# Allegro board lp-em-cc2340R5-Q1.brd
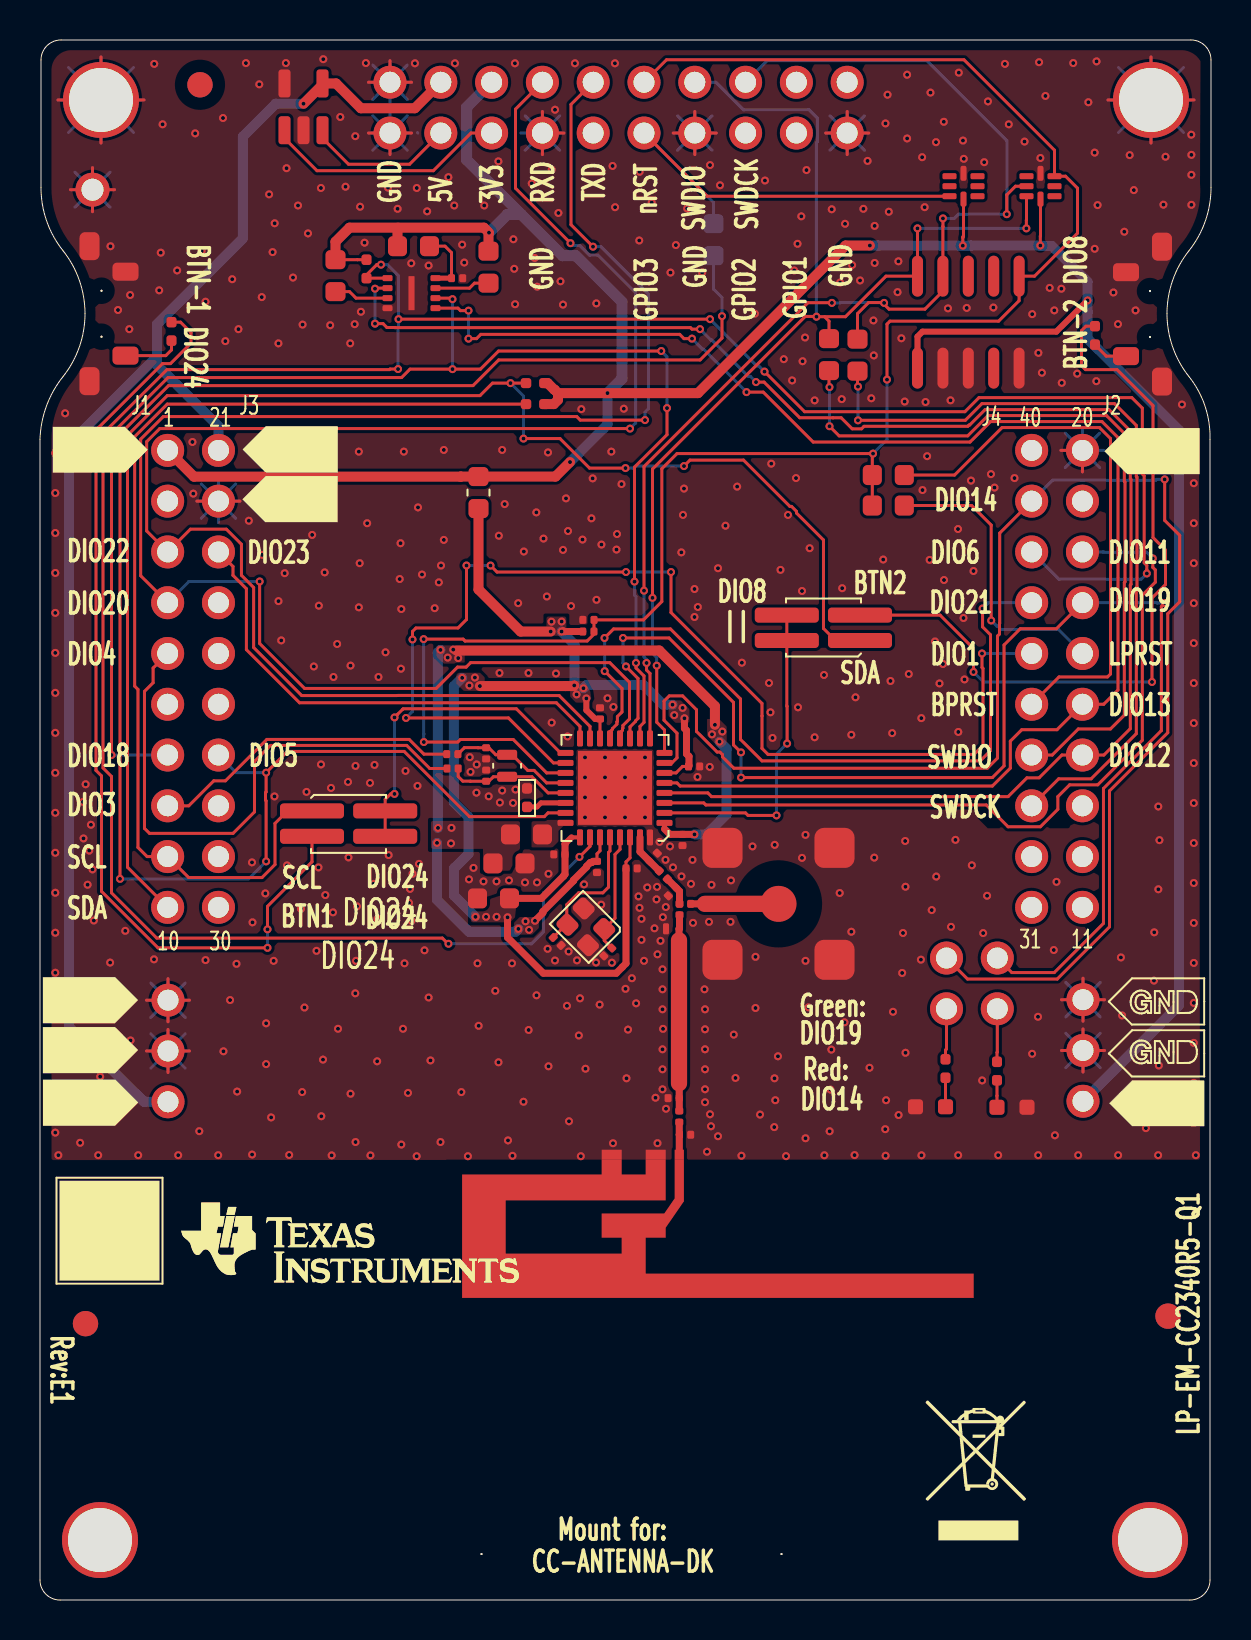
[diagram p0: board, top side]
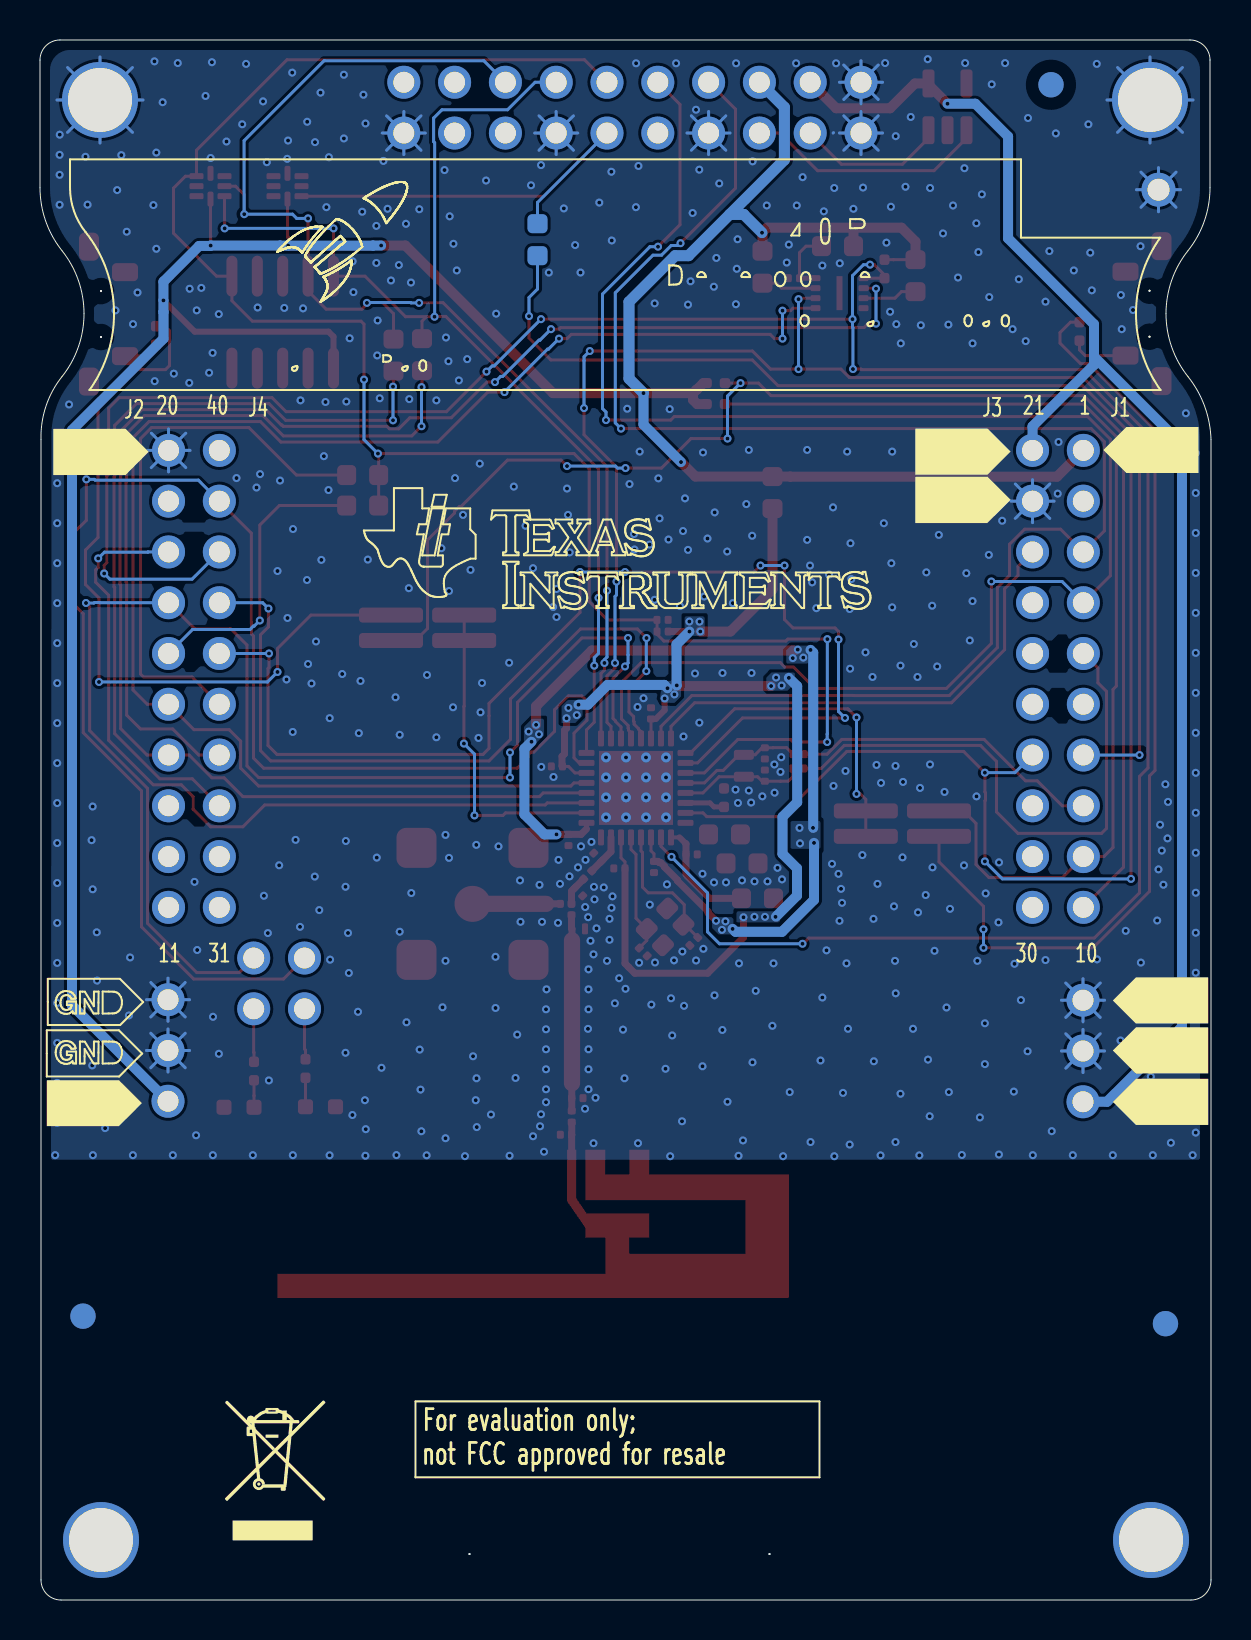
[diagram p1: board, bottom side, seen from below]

Outline 58.55 x 78.04 mm; copper layers: TOP, BOTTOM. Coordinates in mm from the lower left corner of the outline.
Outline path: 0,58.05 0,1 arc(0.29,0.29) 1,0 57.5,0 arc(58.21,0.29) 58.5,1 58.5,58.05 arc(58.25,59.72) 57.45,61.2 arc(56.63,62.68) 56.35,64.35 arc(56.63,66.02) 57.45,67.5 arc(58.27,68.98) 58.55,70.65 58.55,77.04 arc(58.26,77.75) 57.55,78.04 1.05,78.04 arc(0.34,77.75) 0.05,77.04 0.05,70.65 arc(0.33,68.98) 1.15,67.5 arc(1.97,66.02) 2.25,64.35 arc(1.97,62.68) 1.15,61.2 arc(0.32,59.72) 0,58.05

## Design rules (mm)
constraint set DEFAULT: min track width 0.15
nets with their own width: min track width 0.15; nets GND VDDR VDDS WMCU_VDD

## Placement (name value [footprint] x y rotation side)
ANT1  2.4GHz  [ANTENNA_DN007AN]  31.97 22.28 180 top
B1  0  [RESC1608X55A2N]  21.93 54.6 90 top
C9  1uF  [CAPC1005X60B2N]  24.35 39.68 90 top
C33  0.9pF  [CAPC0603X35B2N]  30.86 37.36 225 top
C34  0.9pF  [CAPC0603X35B2N]  31.42 35.23 45 top
C52  7.5pF  [CAPC0603X35B2N]  28.59 32.62 225 top
C53  7.5pF  [CAPC0603X35B2N]  25.66 33.14 315 top
C55  0.1uF  [CAPC0603X35B2N]  20.57 66.12 0 top
C81  12pF  [CAPC0603X35B2N]  22.31 42.63 270 top
C91  15pF  [CAPC0603X35B2N]  22.31 40.96 90 top
C92  0.1uF  [CAPC0603X35B2N]  27.7 49.03 180 top
C99  0.1uF  [CAPC0603X35B2N]  32.43 41.7 0 top
C101  0.1uF  [CAPC0603X35B2N]  28 44.08 90 top
C102  0.1uF  [CAPC0603X35B2N]  29.3 36.6 0 top
C103  0.1uF  [CAPC0603X35B2N]  26.25 37.3 180 top
C104  10uF  [CAPC1608X100A2N]  23.47 35.1 180 top
C105  10uF  [CAPC1608X100A2N]  22.65 36.85 0 top
C106  0.1uF  [CAPC0603X35B2N]  32.12 38.3 270 top
C107  0.1uF  [CAPC0603X35B2N]  27.85 36.95 270 top
CA1  15pF  [CAPC0603X35B2N]  31.97 34.83 0 top
CA2  15pF  [CAPC0603X35B2N]  31.97 34.28 90 top
CR1  LPL296-J2L2-25  [LEDC1707X65N]  49.35 24.65 180 top
CR2  LS L296-P2Q2-1  [LEDC1708X67N]  43.78 24.68 0 top
CR8  TPD6E004RSE  [QFNFC50P150X150X60-8A2N]  50.72 70.23 90 top
CR9  TPD6E004RSE  [QFNFC50P150X150X60-8A2N]  46.88 70.23 90 top
CR10  TPD1E0B04DPY  [SON65P100X60X45-2A2N]  31.3 33.58 0 top
FIDU1  FIDU_1.27mm  [FID127X142]  8 75.8 0 top
FIDU2  FIDU_1.27mm  [FID127X142]  2.28 13.83 0 top
FIDU3  FIDU_1.27mm  [FID127X142]  56.4 14.2 0 top
FIDU4  FIDU_1.27mm  [FID127X142]  8 75.8 180 bottom
FIDU5  FIDU_1.27mm  [FID127X142]  2.28 13.83 180 bottom
FIDU6  FIDU_1.27mm  [FID127X142]  56.4 14.2 180 bottom
J1  SSQ-110-23-L-D  [SAMTEC_SSQ11023LD_A2B]  6.38 57.51 0 bottom
J2  SSQ-110-23-L-D  [SAMTEC_SSQ11023LD_A2B]  49.58 57.51 0 bottom
J7  SMA-10V21-TGG  [HUSTSAN_SMA10V21TGGAN]  36.93 34.83 0 top
L1  10uH  [INDC1608X100A2N]  23.53 38.3 0 top
L33  2.8nH  [INDC0603X33A2N]  30.97 36.47 315 top
LBL1  TI_LOGO  [TI_LOGO_1]  8.06 19.89 0 top
LBL2  TRASH_7mm  [TRASH_7MM]  44.92 2.98 0 top
LBL3  ESD_LABEL_5x5mm  [ESD_LABEL_5X5]  0.97 15.98 0 top
LBL5  -  [LABEL_FOR_EVALUATION_ONLY]  39.63 6.29 180 bottom
M1  SNT-100-BK-G  [SAMTEC_SNT100BKG]  46.57 28.33 90 top
M2  SNT-100-BK-G  [SAMTEC_SNT100BKG]  49.18 28.33 90 top
M3  DCB-10  [MECH_DCB10_A2B]  3 3 0 top
M4  DCB-10  [MECH_DCB10_A2B]  55.5 3 0 top
M5  DCB-10  [MECH_DCB10_A2B]  3.05 75.04 0 top
M6  DCB-10  [MECH_DCB10_A2B]  55.55 75.04 0 top
MH1  HOLE_3.2mm_PTH  [MTG320_380]  3 3 0 top
MH2  HOLE_3.2mm_PTH  [MTG320_380]  55.5 3 0 top
MH3  HOLE_3.2mm_PTH  [MTG320_380]  3.05 75.04 0 top
MH4  HOLE_3.2mm_PTH  [MTG320_380]  55.55 75.04 0 top
MH5  HOLE_1.1mm_PTH  [MTG110_170]  2.62 70.55 0 top
NOREF  -  []  -2.31 22.34 0 top
NOREF#2  -  []  -2.18 27.62 0 top
NOREF#3  -  []  0.28 64.51 0 top
NOREF#4  -  []  -4.3 56.35 0 top
NOREF#5  -  []  53.24 23.47 0 top
NOREF#6  -  []  0.34 77.74 0 top
NOREF#7  -  []  8.46 55.02 0 top
NOREF#8  -  []  -2.18 25.12 0 top
NOREF#9  -  []  0.9 -39.72 0 top
NOREF#10  -  []  51.5 55.05 0 top
NOREF#11  -  []  0.05 75.03 0 top
NOREF#12  -  []  -2.23 77.42 0 top
NOREF#13  -  []  8.4 52.65 0 top
NOREF#14  #VALUE  [unnamed#2]  22.07 2.3 0 top
NOREF#15  -  []  -45.6 -63.8 0 top
NOREF#16  -  []  53.15 0 90 top
NOREF#17  -  []  116.69 68.47 180 bottom
NOREF#18  -  []  6.62 25.08 180 bottom
NOREF#19  -  []  17.1 52.65 180 bottom
NOREF#20  -  []  6.62 27.58 180 bottom
NOREF#21  -  []  58.27 23.64 180 bottom
NOREF#22  -  []  5.6 56.15 180 bottom
NOREF#23  -  []  6.57 22.38 180 bottom
NOREF#24  -  []  17.24 54.91 180 bottom
NOREF#25  -  []  51.53 78.57 180 bottom
NOREF#26  -  []  60.2 55.05 180 bottom
P1  BB02-HC031-KB1-603000  [GRADCONN_BB02HC031KB1603000_A2B]  52.15 24.95 90 top
P2  BB02-HJ041-KB1-603000  [GRADCONN_BB02HJ041KB1603000_A2B]  45.32 29.58 0 top
P3  CNT-F254-210-GD-850/3.2  [CNT_CNTF254210GD85032_A2B]  17.5 75.93 0 top
P4  FTSH-105-01-F-DV-K  [SAMTEC_FTSH-105-01-F-DV-K-10L]  43.88 61.62 0 top
P5  BB02-HC031-KB1-603000  [GRADCONN_BB02HC031KB1603000_A2B]  6.4 24.93 90 top
P6  FTS-102-01-F-DV  [SAMTEC_FTS10201FDV_A2N]  13.6 39.48 270 top
P7  FTS-102-01-F-DV  [SAMTEC_FTS10201FDV_A2N]  41 48 90 top
R1  100k  [RESC0603X35B2N]  27.7 48.45 180 top
R4  0  [RESC1608X55A2N]  39.45 61.5 90 top
R5  0  [RESC1608X55A2N]  40.88 61.48 90 top
R6  0  [RESC0603X35B2N]  20.9 42.31 180 top
R7  0  [RESC0603X35B2N]  20.35 41.6 0 top
R14  180  [RESC1005X40B2N]  45.28 26.12 90 top
R15  220  [RESC1005X40B2N]  47.85 26 90 top
R21  0  [RESC1608X55A2N]  33.68 67.25 90 bottom
R22  0  [RESC1608X55A2N]  22.43 67.48 270 top
R23  0  [RESC1608X55A2N]  14.78 67.05 270 top
R24  2.2k  [RESC1005X40B2N]  16.32 66.12 90 top
R25  0  [RESC1608X55A2N]  19.47 67.73 180 top
R51  0  [RESC1608X55A2N]  43.22 54.75 180 top
R52  0  [RESC1608X55A2N]  43.22 56.28 180 top
R55  100  [RESC1005X40B2N]  52.75 62.8 90 top
R56  100  [RESC1005X40B2N]  6.57 63 90 top
R66  3.3k  [RESC1005X40B2N]  24.3 60.88 0 top
R67  3.3k  [RESC1005X40B2N]  24.3 59.83 0 top
SW1  1188E-1K2  [SW_1188E1K2V_A2N]  2.47 67.73 270 top
SW2  1188E-1K2  [SW_1188E1K2V_A2N]  56.1 60.95 90 top
U1  CC2340R52E0RHB  [QFNFC50P500X500X100-33B2N]  31.22 38.88 90 top
U3  MX25R8035FZUIL0  [SON50P300X200X60-9B2N]  17.38 66.12 270 top
U4  CAT24C08TDI  [SOT95P280X100-5A2N]  12.22 73.53 0 top
UNK#REFDES  #VALUE  []  46.65 66.21 180 bottom
Y1  32.768KHz  [XTAL_TZ3359DAAO73_A2N]  23.36 42.28 270 top
Y2  48MHz  [OSCCC205X165X50-4A2N]  28.21 33.57 135 top
Z60  TBD  [CAPC0603X35B2N]  31.96 25.11 180 top
Z61  0  [RESC0603X35B2N]  31.96 23.91 90 top
Z62  TBD  [CAPC0603X35B2N]  31.97 23.28 0 top

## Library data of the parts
ANT1 = ANTENNA_DN007
B1 R4 R5 R21-R23 R25 R51 R52 = RESISTOR: User Part Number: #PN; alternate symbols: (RESC1608X55A2L,RESC1608X55A2M)
C9 = CAPACITOR: User Part Number: #PN
C33 C34 C52 C53 C55 C81 C91 C92 C99 C101-C103 C106 C107 CA1 CA2 Z60 Z62 = CAPACITOR: User Part Number: #PN; alternate symbols: (CAPC0603X35B2L,CAPC0603X35B2M)
C104 C105 = CAPACITOR: User Part Number: #PN; alternate symbols: (CAPC1608X100A2L,CAPC1608X100A2M)
CR1 = LED: alternate symbols: (LEDC1707X65L,LEDC1707X65M)
CR2 = LED: alternate symbols: (LEDC1708X67L,LEDC1708X67M)
CR8 CR9 = DIODE_TVS_TPD6E004_QFN8_V1: User Part Number: #PN; alternate symbols: (QFNFC50P150X150X60-8A2L,QFNFC50P150X150X60-8A2M)
CR10 = DIODE_TVS_BIDIR_S: User Part Number: #PN
FIDU1-FIDU6 = FIDMARK
J1 J2 = CONN_HEADER_2X10_J_S_V1: User Part Number: #PN; alternate symbols: (SAMTEC_SSQ11023LD_A2C,SAMTEC_SSQ11023LD_A2A)
J7 = CONN_COAX_1_4: alternate symbols: (HUSTSAN_SMA10V21TGGL,HUSTSAN_SMA10V21TGGM)
L1 = IND_CORE: User Part Number: #PN; alternate symbols: (INDC1608X100A2L,INDC1608X100A2M)
L33 = INDUCTOR: User Part Number: #PN; alternate symbols: (INDC0603X33A2L,INDC0603X33A2M)
LBL1 = TI_LOGO_V1
LBL2 = TRASH_V2: User Part Number: #PN
LBL3 = ESD_LABEL: User Part Number: #PN
LBL5 = LABEL_FOR_EVALUATOIN_ONLY: User Part Number: #PN
M1 M2 = MECH_SHUNT_JUMPER_V1: User Part Number: #PN
M3-M6 = MECH_SPACERS_SUPPORT_V1: User Part Number: #PN
MH1-MH5 = HOLE_PTH
NOREF#14 UNK#REFDES = -: User Part Number: #PN
P1 P5 = CONN_HEADER_3_P_S: User Part Number: #PN; alternate symbols: (GRADCONN_BB02HC031KB1603000_A2C,GRADCONN_BB02HC031KB1603000_A2A)
P2 = CONN_HEADER_2X2_P: User Part Number: #PN; alternate symbols: (GRADCONN_BB02HJ041KB1603000_A2C,GRADCONN_BB02HJ041KB1603000_A2A)
P3 = CONN_HEADER_2X10_J_S_V1: User Part Number: #PN; alternate symbols: (CNT_CNTF254210GD85032_A2A,CNT_CNTF254210GD85032_A2C)
P4 = CONN_HEADER_2X5: alternate symbols: (SAMTEC_FTSH10501FDVK_A2L,SAMTEC_FTSH10501FDVK_A2M)
P6 P7 = CONN_HEADER_2X2_P_V2: User Part Number: #PN; alternate symbols: (SAMTEC_FTS10201FDV_A2L,SAMTEC_FTS10201FDV_A2M)
R1 R6 R7 Z61 = RESISTOR: User Part Number: #PN; alternate symbols: (RESC0603X35B2L,RESC0603X35B2M)
R14 R15 R24 R55 R56 R66 R67 = RESISTOR: User Part Number: #PN
SW1 SW2 = SWITCH_TACT_V2: alternate symbols: (SW_1188E1K2V_A2L,SW_1188E1K2V_A2M)
U1 = IC_CC2340R52E0RHB_VQFN32: User Part Number: #PN; alternate symbols: (QFNFC50P500X500X100-33B2L,QFNFC50P500X500X100-33B2M)
U3 = IC_FLASH_MX25R8035F_USON8: User Part Number: #PN; alternate symbols: (SON50P300X200X60-9B2L,SON50P300X200X60-9B2M)
U4 = IC_EEPROM_CAT24C08_TSOT23-5: User Part Number: #PN; alternate symbols: (SOT95P280X100-5A2L,SOT95P280X100-5A2M)
Y1 = XTAL: User Part Number: #PN; alternate symbols: (XTAL_TZ3359DAAO73_A2L,XTAL_TZ3359DAAO73_A2M)
Y2 = XTAL_4PINS_1_3: User Part Number: #PN; alternate symbols: (OSCCC205X165X50-4A2L,OSCCC205X165X50-4A2M)

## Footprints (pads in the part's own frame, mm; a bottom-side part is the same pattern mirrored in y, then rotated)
ANTENNA_DN007AN
  rect 0.46x0.5 smd: 1(0,0)
  rect 1.001x0.5 smd: 2(1.18,0) 3(3.38,0)
CAPC0603X35B2N
  custom 0.087x0.087 smd: 1(0,0) 2(0.56,0)
CAPC1005X60B2N
  custom 0.125x0.125 smd: 1(0,0) 2(0.924,0)
CAPC1608X100A2N
  custom 0.237x0.237 smd: 1(0,0) 2(1.6,0)
CNT_CNTF254210GD85032_A2B
  round 1.65 hole 1.05: 1(0,0) 2(0,-2.54) 3(2.54,0) 4(2.54,-2.54) 5(5.08,0) 6(5.08,-2.54) 7(7.62,0) 8(7.62,-2.54) 9(10.16,0) 10(10.16,-2.54) 11(12.7,0) 12(12.7,-2.54) 13(15.24,0) 14(15.24,-2.54) 15(17.78,0) 16(17.78,-2.54) 17(20.32,0) 18(20.32,-2.54) 19(22.86,0) 20(22.86,-2.54)
FID127X142
  round 1.27 smd: 1(0,0)
GRADCONN_BB02HC031KB1603000_A2B
  round 1.65 hole 1.05: 1(0,0) 2(2.54,0) 3(5.08,0)
GRADCONN_BB02HJ041KB1603000_A2B
  round 1.65 hole 1.05: 1(0,0) 2(0,2.54) 3(2.54,0) 4(2.54,2.54)
HUSTSAN_SMA10V21TGGAN
  round 1.8 smd: 1(0,0)
  custom 0.5x0.5 smd: 2(-2.8,-2.8) 3(2.8,-2.8) 4(2.8,2.8) 5(-2.8,2.8)
INDC0603X33A2N
  custom 0.087x0.087 smd: 1(0,0) 2(0.56,0)
INDC1608X100A2N
  custom 0.237x0.237 smd: 1(0,0) 2(1.6,0)
LEDC1707X65N
  custom 0.188x0.188 smd: 1(0,0) 2(1.501,0)
LEDC1708X67N
  custom 0.188x0.188 smd: 1(0,0) 2(1.501,0)
MTG110_170
  round 1.699 hole 1.1: 1(0,0)
MTG320_380
  round 3.8 hole 3.2: 1(0,0)
OSCCC205X165X50-4A2N
  custom 0.212x0.212 smd: 1(0,0) 2(1.45,0) 3(1.45,1.15) 4(0,1.15)
QFNFC50P150X150X60-8A2N
  custom 0.075x0.075 smd: 1(0,0) 2(0.5,0) 3(1,0) 4(1.145,0.7) 5(1,1.4) 6(0.5,1.4) 7(0,1.4) 8(-0.145,0.7)
QFNFC50P500X500X100-33B2N
  custom 0.075x0.075 smd: 1(0,0) 2(0.5,0) 3(1,0) 4(1.5,0) 5(2,0) 6(2.5,0) 7(3,0) 8(3.5,0) 9(4.225,0.725) 10(4.225,1.225) 11(4.225,1.725) 12(4.225,2.225) 13(4.225,2.725) 14(4.225,3.225) 15(4.225,3.725) 16(4.225,4.225) 17(3.5,4.95) 18(3,4.95) 19(2.5,4.95) 20(2,4.95) 21(1.5,4.95) 22(1,4.95) 23(0.5,4.95) 24(0,4.95) 25(-0.725,4.225) 26(-0.725,3.725) 27(-0.725,3.225) 28(-0.725,2.725) 29(-0.725,2.225) 30(-0.725,1.725) 31(-0.725,1.225) 32(-0.725,0.725)
  rect 3.7x3.7 smd: 33(1.75,2.475)
RESC0603X35B2N
  custom 0.087x0.087 smd: 1(0,0) 2(0.56,0)
RESC1005X40B2N
  custom 0.125x0.125 smd: 1(0,0) 2(0.924,0)
RESC1608X55A2N
  custom 0.237x0.237 smd: 1(0,0) 2(1.6,0)
SAMTEC_FTS10201FDV_A2N
  custom 0.188x0.188 smd: 1(0,0) 2(0,3.66) 3(1.27,0) 4(1.27,3.66)
SAMTEC_FTSH-105-01-F-DV-K-10L
  oval 0.551x2.05 smd: 1(0,0) 2(0,4.6) 3(1.27,0) 4(1.27,4.6) 5(2.54,0) 6(2.54,4.6) 7(3.81,0) 8(3.81,4.6) 9(5.08,0) 10(5.08,4.6)
SAMTEC_SSQ11023LD_A2B
  round 1.65 hole 1.05: 1(0,0) 2(2.54,0) 3(0,2.54) 4(2.54,2.54) 5(0,5.08) 6(2.54,5.08) 7(0,7.62) 8(2.54,7.62) 9(0,10.16) 10(2.54,10.16) 11(0,12.7) 12(2.54,12.7) 13(0,15.24) 14(2.54,15.24) 15(0,17.78) 16(2.54,17.78) 17(0,20.32) 18(2.54,20.32) 19(0,22.86) 20(2.54,22.86)
SON50P300X200X60-9B2N
  custom 0.075x0.075 smd: 1(0,0) 2(0.5,0) 3(1,0) 4(1.5,0) 5(1.5,2.4) 6(1,2.4) 7(0.5,2.4) 8(0,2.4)
  rect 1.7x0.3 smd: 9(0.75,1.2)
SON65P100X60X45-2A2N
  custom 0.075x0.075 smd: 1(0,0) 2(0.65,0)
SOT95P280X100-5A2N
  custom 0.15x0.15 smd: 1(0,0) 2(0.95,0) 3(1.9,0) 4(1.9,2.34) 5(0,2.34)
SW_1188E1K2V_A2N
  round 0.099 hole 0.899 unplated: (2.229,0.6) (4.529,0.6)
  custom 0.25x0.25 smd: 1(0,0) 2(6.75,0)
  custom 0.225x0.225 smd: 3(1.275,1.8) 4(5.475,1.8)
unnamed#2
  round 0.099 hole 3.2 unplated: (0,0) (15,0)
XTAL_TZ3359DAAO73_A2N
  custom 0.125x0.125 smd: 1(0,0) 2(1.1,0)

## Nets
5V0_BP: J1.2 P3.3 P5.1 U4.4
GND: ANT1.2 ANT1.3(GND_3) C9.2 C33.1 C34.1 C52.2 C53.2 C55.2 C81.2 C91.2 C92.2 C99.2 C101.2 C102.2 C103.2 C104.2 C105.2 C106.2 C107.2 CR1.1(C) CR2.1(C) CR8.4 CR9.4 CR10.1 J1.4 J2.2 J7.2 J7.3 J7.4 J7.5 MH3.1 MH4.1 MH5.1 P1.2 P1.3 P3.1 P3.2 P3.8 P3.14 P3.20 P4.3 P4.5 P4.9 P5.2 P5.3 SW1.1 SW1.2 SW1.3 SW2.1 SW2.2 SW2.4 U1.32 U1.33 U3.4 U3.9 U4.2 U4.5(WP) Y2.2 Y2.4(GND#4) Z60.2 Z62.2
VDDR: C105.1 C106.1 C107.1 L1.1 U1.1 U1.27
VDDS: B1.1 C99.1 C101.1 C102.1 C103.1 C104.1 R1.2 U1.6 U1.14 U1.25 U1.30
BP_RESET: J2.11 R52.1
BTN1: P6.3 R56.2
BTN2: P7.3 R55.2
DCDC: L1.2 U1.24
DIO1_RTS: J2.9 U1.18
DIO3: J1.15 R6.2
DIO4: J1.9 R7.1
DIO5_A2: J1.14 R21.1 U1.23
DIO6_FLASH_CS: J2.5 R24.1 U1.26 U3.1
DIO8_SDA: P7.2 P7.4 U1.2(DIO8)
DIO11_CS: J2.6 U1.3
DIO12_MISO: J2.14 U1.4 U3.2
DIO13_MOSI: J2.12 U1.5 U3.5
DIO14_RLED: J2.3 P2.2 U1.7
DIO18_SCLK: J1.13 U1.10 U3.6
DIO19_GLED: J2.8 P2.4 U1.11
DIO21_CTS: J2.7 U1.13
DIO23_A8: J1.6 U1.16
DIO24_SCL: P6.2 P6.4 U1.17
LP_RESET: J2.10 R51.1
SCL: J1.17 P6.1 R67.1
SDA: J1.19 P7.1 R66.1
WMCU_RESET: C92.1 CR8.3 P3.11 P4.10 R1.1 R51.2 R52.2 U1.19
WMCU_RXD: J1.5 P3.7 U1.15
WMCU_SWDCK: CR8.6 P3.15 P4.4 R5.2 U1.9
WMCU_SWDIO: CR8.7 P3.13 P4.2 R4.2 U1.8
WMCU_TXD: J1.7 P3.9 U1.12
WMCU_VDD: B1.2 CR8.8(VCC) CR9.8(VCC) J1.1 P1.1 P3.5 P4.1 R22.1 R23.1 R24.2 R25.2 R66.2 R67.2
XDS_BOARDID_SCL: P3.6 U4.1
XDS_BOARDID_SDA: P3.4 U4.3
XDS_GPIO3: CR9.7 P3.12 R21.2
N3101199: C81.1 R6.1 U1.20 Y1.1
N3101441: C52.1 U1.29 Y2.1
N3101453: C53.1 U1.28 Y2.3
N3109894: J2.13 R4.1
N3109960: J2.15 R5.1
N3110356: P2.1 R14.2
N3110380: P2.3 R15.2
N3110768: R56.1 SW1.4
N3110772: R55.1 SW2.3
N3110876: CR1.2 R15.1
N3110880: CR2.2 R14.1
N3111246: C55.1 R25.1 U3.8(VCC)
N3111262: R22.2 U3.7
N3111266: R23.2 U3.3
N3241033: C91.1 R7.2 U1.21 Y1.2
N3275984: CA1.2 J7.1
N3375988: C34.2 CA1.1 CA2.2 L33.2
N3377063: CA2.1 CR10.2 Z60.1 Z61.2
N3377070: ANT1.1 Z61.1 Z62.1
N3512302: C33.2 L33.1 U1.31
N3566095: C9.1 U1.22

Pads without a net: CR8 1 2 5; CR9 1 2 3 5 6; FIDU1 1; FIDU2 1; FIDU3 1; FIDU4 1; FIDU5 1; FIDU6 1; J1 3 8 10 11 12 16 18 20; J2 1 4 16 17 18 19 20; MH1 1; MH2 1; P3 10 16 17 18 19; P4 6 7 8

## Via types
v1: diameter 0.4, hole 0.2, TOP to BOTTOM, 691 vias
v2: diameter 0.5, hole 0.201, TOP to BOTTOM, 16 vias

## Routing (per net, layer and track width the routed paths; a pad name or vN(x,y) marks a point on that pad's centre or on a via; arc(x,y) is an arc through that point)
5V0_BP: length 72.7
  TOP w0.5: v1(13.18,74.85) 14.12,75.8 U4.4 14.8,75.87 16.04,74.62 18.74,74.62 P3.3
  BOTTOM w0.5: 5.85,62.2 1.7,58.05 1.7,57.98 1.45,57.73 1.45,28.67 5.2,24.93 P5.1 ; 5.85,62.2 5.85,63.82 10.15,68.12 10.15,73.21 11.78,74.85 v1(13.18,74.85) ; 5.85,62.2 5.85,61.79 8.92,58.71 J1.2
GND: length 207.5
  TOP w0.15: P1.2 53.23,27.49 ; P1.2 51.07,27.49 ; P1.2 52.15,28.57 ; P1.2 52.15,26.41 ; MH3.1 5.2,75.04 ; MH3.1 3.05,72.89 ; MH3.1 0.9,75.04 ; MH3.1 3.05,77.19 ; P3.20 40.36,74.46 ; P3.20 40.36,72.31 ; P3.20 41.44,73.38 ; P3.20 39.28,73.38 ; MH5.1 2.62,71.65 ; MH5.1 2.62,69.45 ; MH5.1 1.52,70.55 ; MH5.1 3.73,70.55 ; P3.8 25.12,74.46 ; P3.8 25.12,72.31 ; P3.8 26.2,73.38 ; 32.74,72.31 P3.14 ; P3.14 33.82,73.38 ; P3.14 31.66,73.38 ; P3.14 32.74,74.46 ; MH4.1 57.7,75.04 ; MH4.1 55.55,77.19 ; MH4.1 53.4,75.04 ; MH4.1 55.55,72.89 ; P1.3 53.23,30.03 ; P1.3 52.15,28.95 ; P1.3 51.07,30.03 ; P1.3 52.15,31.11 ; P3.1 18.58,75.93 ; P3.1 16.42,75.93 ; P3.1 17.5,77 ; 6.4,26.39 P5.2 ; P5.2 6.4,28.54 ; P5.2 5.32,27.47 ; P5.2 7.48,27.47 ; 17.5,72.31 P3.2 ; P3.2 18.58,73.38 ; P3.2 16.42,73.38 ; 6.4,28.93 P5.3 ; P5.3 5.32,30.01 ; P5.3 7.48,30.01 ; P5.3 6.4,31.08 ; 10,54.97 J1.4 7.85,54.97 ; 51.05,57.51 J2.2 52.12,56.43
  BOTTOM w0.15: 3.05,72.89 MH3.1 ; MH3.1 1.43,76.66 ; MH3.1 3.05,77.19 ; MH3.1 4.67,73.42 ; MH3.1 1.43,73.42 ; MH3.1 0.9,75.04 ; MH3.1 5.2,75.04 ; MH3.1 4.67,76.66 ; P1.2 53.23,27.49 ; P1.2 51.29,28.35 ; P1.2 51.29,26.63 ; P1.2 53.01,28.35 ; P1.2 51.07,27.49 ; P1.2 53.01,26.63 ; P1.2 52.15,28.57 ; P1.2 52.15,26.41 ; P3.1 18.58,75.93 ; P3.1 16.42,75.93 ; P3.1 16.64,75.06 ; P3.1 18.36,76.79 ; P3.1 17.5,74.85 ; P3.1 16.64,76.79 ; P3.1 18.36,75.06 ; P3.1 17.5,77 ; 5.32,30.01 P5.3 ; P5.3 5.54,29.14 ; P5.3 6.4,31.08 ; P5.3 5.54,30.87 ; P5.3 7.26,30.87 ; P5.3 6.4,28.93 ; P5.3 7.26,29.14 ; P5.3 7.48,30.01 ; 24.04,73.38 P3.8 ; P3.8 25.98,74.25 ; P3.8 25.98,72.52 ; P3.8 25.12,72.31 ; P3.8 24.26,72.52 ; P3.8 26.2,73.38 ; P3.8 24.26,74.25 ; P3.8 25.12,74.46 ; 40.36,72.31 P3.20 ; P3.20 39.5,72.52 ; P3.20 39.5,74.25 ; P3.20 39.28,73.38 ; P3.20 41.22,74.25 ; P3.20 41.44,73.38 ; P3.20 41.22,72.52 ; P3.20 40.36,74.46 ; 55.55,72.89 MH4.1 ; MH4.1 57.17,73.42 ; MH4.1 57.17,76.66 ; MH4.1 55.55,77.19 ; MH4.1 53.93,73.42 ; MH4.1 53.93,76.66 ; MH4.1 57.7,75.04 ; MH4.1 53.4,75.04 ; 32.74,72.31 P3.14 ; P3.14 32.74,74.46 ; P3.14 33.82,73.38 ; P3.14 31.88,74.25 ; P3.14 33.6,74.25 ; P3.14 31.66,73.38 ; P3.14 33.6,72.52 ; P3.14 31.88,72.52 ; P3.2 17.5,74.46 ; P3.2 18.36,72.52 ; P3.2 16.42,73.38 ; P3.2 16.64,74.25 ; P3.2 18.58,73.38 ; P3.2 17.5,72.31 ; P3.2 16.64,72.52 ; P3.2 18.36,74.25 ; P1.3 53.01,29.17 ; P1.3 51.29,29.17 ; P1.3 51.29,30.89 ; P1.3 51.07,30.03 ; P1.3 52.15,31.11 ; P1.3 52.15,28.95 ; P1.3 53.01,30.89 ; P1.3 53.23,30.03 ; 51.26,56.65 J2.2 ; J2.2 53.2,57.51 ; J2.2 52.99,56.65 ; J2.2 52.12,56.43 ; J2.2 51.05,57.51 ; J2.2 52.12,58.59 ; J2.2 51.26,58.37 ; J2.2 52.99,58.37 ; 1.75,71.43 MH5.1 ; MH5.1 3.5,69.67 ; MH5.1 1.52,70.55 ; MH5.1 2.62,71.65 ; MH5.1 1.75,69.67 ; MH5.1 3.5,71.43 ; MH5.1 2.62,69.45 ; MH5.1 3.73,70.55 ; J1.4 10,54.97 ; J1.4 8.92,53.89 ; J1.4 8.06,54.11 ; J1.4 8.92,56.05 ; J1.4 7.85,54.97 ; J1.4 9.78,54.11 ; J1.4 9.78,55.83 ; J1.4 8.06,55.83 ; P5.2 7.48,27.47 ; P5.2 7.26,28.33 ; P5.2 6.4,26.39 ; P5.2 7.26,26.6 ; P5.2 6.4,28.54 ; P5.2 5.54,26.6 ; P5.2 5.32,27.47 ; P5.2 5.54,28.33 ; 18.89,73.38 18.88,73.4
  vias: v1(0.76,57.38) v1(0.76,55.38) v1(0.76,53.38) v1(0.76,51.38) v1(0.76,49.38) v1(0.76,47.38) v1(0.76,45.38) v1(0.76,43.38) v1(0.76,41.38) v1(0.76,39.38) v1(0.76,37.38) v1(0.76,35.38) v1(0.76,33.38) v1(0.76,31.38) v1(0.76,29.38) v1(0.76,27.38) v1(0.76,25.38) v1(0.76,23.38) v1(0.92,22.25) v1(1.26,59.37) v1(2.01,22.87) v1(2.15,39.93) v1(2.18,38.1) v1(2.28,40.81) v1(2.38,35.78) v1(2.55,38.78) v1(2.46,37.49) v1(2.62,36.55) v1(2.69,33.99) v1(2.91,22.25) v1(2.98,30.08) v1(3.01,26.18) v1(3.52,67.72) v1(3.51,31.89) v1(3.55,24.1) v1(3.9,64.53) v1(4.26,33.48) v1(4.51,65.28) v1(4.46,63.57) v1(4.53,27.99) v1(4.91,22.25) v1(5.71,76.84) v1(5.7,32.05) v1(6.04,67.4) v1(5.96,65.52) v1(6.13,73.82) v1(6.86,66.51) v1(6.91,22.25) v1(7.62,57.93) v1(7.66,55.35) v1(7.76,73.37) v1(7.96,23.45) v1(8.08,67.48) v1(8.28,64.95) v1(8.28,32.01) v1(8.91,22.25) v1(9.15,74.14) v1(9.17,27.45) v1(9.27,62.98) v1(9.5,30.01) v1(9.61,66.07) v1(9.82,31.83) v1(9.92,63.57) v1(9.86,25.43) v1(10.3,76.88) v1(10.44,55.07) v1(10.44,53.99) v1(10.6,36.9) v1(10.62,33.9) v1(10.6,22.29) v1(10.96,75.82) v1(11.09,65.18) v1(11.11,52.28) v1(11.23,57.57) v1(11.27,35.35) v1(11.31,28.85) v1(11.31,26.81) v1(11.46,70.32) v1(11.63,67.43) v1(11.56,24.14) v1(11.73,68.87) v1(11.72,40.2) v1(11.68,31.97) v1(11.92,62.86) v1(11.92,49.97) v1(12.06,48) v1(12.23,51.37) v1(12.29,76.89) v1(12.33,71.63) v1(12.35,36.75) v1(12.36,54.49) v1(12.46,22.26) v1(12.65,66.16) v1(12.9,69.76) v1(13.13,63.8) v1(13.05,34.58) v1(13.11,25.41) v1(13.22,29.64) v1(13.32,40.43) v1(13.4,68.36) v1(13.61,53.28) v1(13.69,57.57) v1(13.69,46.7) v1(13.82,32.48) v1(13.94,49.74) v1(13.93,36.65) v1(14.05,70.64) v1(14.05,41.8) v1(14.07,24.2) v1(14.16,77.08) v1(14.23,51.41) v1(14.15,27.03) v1(14.27,35.27) v1(14.51,63.77) v1(14.55,54.78) v1(14.55,40.62) v1(14.58,22.24) v1(14.68,46.18) v1(14.65,34.4) v1(14.86,47.82) v1(14.9,28.58) v1(15.01,74.19) v1(15.28,70.7) v1(15.4,40.93) v1(15.43,37.15) v1(15.51,62.86) v1(15.53,46.74) v1(15.53,25.33) v1(15.73,63.82) v1(15.76,73.23) v1(15.78,41.73) v1(15.85,34.7) v1(15.8,31.98) v1(15.76,30.35) v1(15.78,22.91) v1(15.94,57.45) v1(15.94,49.66) v1(16,69.7) v1(16.05,64.44) v1(15.98,51.87) v1(16.23,67.9) v1(16.29,76.89) v1(16.36,53.87) v1(16.5,40.88) v1(16.52,22.24) v1(16.72,41.78) v1(16.68,35.83) v1(16.93,46.18) v1(16.88,34.08) v1(16.86,26.95) v1(17.28,47.41) v1(17.4,70.66) v1(17.43,37.27) v1(17.88,69.59) v1(18.03,52.87) v1(17.98,51.07) v1(18.05,46.59) v1(18.07,49.57) v1(18.07,22.78) v1(18.19,57.45) v1(18.22,31.85) v1(18.15,28.58) v1(18.28,41.48) v1(18.45,34.88) v1(18.4,25.37) v1(18.5,35.58) v1(18.56,66.87) v1(18.62,36.33) v1(18.57,33.98) v1(18.75,76.87) v1(18.84,70.64) v1(18.83,22.2) v1(18.9,54.66) v1(18.88,40.73) v1(18.95,36.83) v1(19.1,51.3) v1(19.22,32.5) v1(19.36,69.47) v1(19.43,66.76) v1(19.43,30.14) v1(19.52,26.99) v1(19.73,49.62) v1(19.94,50.91) v1(20.02,22.91) v1(20.05,51.75) v1(20.19,57.53) v1(20.19,53.03) v1(20.42,71.18) v1(20.75,76.87) v1(20.71,69.76) v1(21.11,67.8) v1(21.07,25.41) v1(21.21,66.91) v1(21.45,36.05) v1(21.4,22.2) v1(21.49,42.16) v1(21.53,41.43) v1(21.68,36.62) v1(21.83,41.8) v1(21.82,40.39) v1(21.88,31.85) v1(21.93,28.72) v1(22.21,69.76) v1(22.18,35.95) v1(22.43,40.2) v1(22.82,35.95) v1(22.76,30.47) v1(22.92,71.97) v1(22.94,53.24) v1(22.93,26.9) v1(22.97,46.38) v1(22.99,39.89) v1(23.11,57.53) v1(23.11,40.49) v1(23.23,54.82) v1(23.45,36) v1(23.4,22.99) v1(23.6,31.85) v1(23.62,22.22) v1(23.75,76.87) v1(23.67,68.07) v1(23.71,66.59) v1(23.65,39.87) v1(23.75,64.82) v1(23.77,40.54) v1(23.91,49.87) v1(24.19,52.45) v1(24.25,35.9) v1(24.18,24.93) v1(24.43,46.38) v1(24.43,28.52) v1(24.59,70.86) v1(24.73,67.14) v1(24.82,54.41) v1(24.85,35.9) v1(24.82,30.25) v1(24.86,65.7) v1(25.18,53.1) v1(25.34,50.2) v1(25.4,57.41) v1(25.43,36.33) v1(25.38,32.58) v1(25.43,26.7) v1(25.59,71.55) v1(25.58,43.89) v1(25.75,31.99) v1(25.75,74.55) v1(25.8,46.35) v1(25.92,69.39) v1(26.02,65.97) v1(26.15,64.8) v1(26.15,52.53) v1(26.3,55.11) v1(26.35,29.72) v1(26.4,53.48) v1(26.38,43.2) v1(26.43,32.44) v1(26.45,23.95) v1(26.55,49.72) v1(26.75,76.87) v1(26.85,32) v1(26.94,28.24) v1(27,30.1) v1(27.04,22.2) v1(27.07,59.57) v1(27.12,53.05) v1(27.2,35.8) v1(27.27,26.58) v1(27.63,56.11) v1(27.57,54.11) v1(27.82,64.86) v1(27.82,50.03) v1(27.8,31.89) v1(27.98,29.78) v1(28.07,52.8) v1(28.06,34.79) v1(28.38,45.11) v1(28.63,71.74) v1(28.57,57.45) v1(28.59,31.88) v1(28.75,76.87) v1(28.67,44.68) v1(28.65,22.85) v1(28.75,69.68) v1(28.85,53.33) v1(28.82,52.55) v1(29.07,55.83) v1(29.19,59.59) v1(29.28,30.58) v1(29.32,26.1) v1(29.4,28.53) v1(29.59,31.11) v1(29.81,29.85) v1(29.93,35.2) v1(29.98,71.45) v1(29.96,68.01) v1(29.97,34.62) v1(30.07,34.08) v1(30.07,33.03) v1(30.2,31.98) v1(30.36,35.65) v1(30.59,69.91) v1(30.72,33.6) v1(30.82,35.05) v1(30.78,25.12) v1(30.85,35.68) v1(30.88,32.3) v1(30.88,22.85) v1(30.98,37.93) v1(31.03,32.98) v1(31.14,34.16) v1(31.12,31.55) v1(31.12,30.55) v1(31.12,29.55) v1(31.12,27.55) v1(31.12,26.55) v1(31.12,25.55) v1(31.15,28.57) v1(31.27,37.03) v1(31.29,34.67) v1(31.3,24.58) v1(31.52,66.41) v1(31.5,37.7) v1(31.65,36.65) v1(31.79,67.78) v1(32.07,52.41) v1(32.07,36.2) v1(32.2,55.6) v1(32.15,54.28) v1(32.36,69.61) v1(32.62,37.03) v1(32.55,35.83) v1(32.72,50.58) v1(32.72,49.18) v1(32.65,33.88) v1(32.89,49.68) v1(32.88,41.17) v1(33.11,66.41) v1(33.22,30.55) v1(33.25,29.55) v1(33.25,28.55) v1(33.25,27.55) v1(33.25,26.55) v1(33.25,25.55) v1(33.25,24.9) v1(33.35,22.43) v1(33.45,33.93) v1(33.5,71.78) v1(33.49,41.68) v1(33.5,24.3) v1(33.57,35.78) v1(33.55,23.7) v1(33.9,51.62) v1(33.9,23.2) v1(34,70.77) v1(34.27,53.74) v1(34.53,33.93) v1(34.55,36) v1(34.69,28.28) v1(34.77,26.12) v1(34.86,55.7) v1(35.09,46.89) v1(35.07,22.23) v1(35.62,37.7) v1(35.74,64.35) v1(35.78,32.18) v1(35.77,29.62) v1(36,24.28) v1(36.25,71.01) v1(36.45,45.88) v1(36.52,44.41) v1(36.56,56.85) v1(36.62,43.12) v1(36.74,37.78) v1(36.72,26.1) v1(36.71,23.66) v1(36.76,25) v1(36.9,27.2) v1(37.02,51.53) v1(37.19,62.07) v1(37.3,22.21) v1(37.4,54.28) v1(37.61,61.01) v1(37.71,66.51) v1(37.8,56.12) v1(37.88,67.84) v1(37.9,44.66) v1(38.07,69.22) v1(38.13,61.97) v1(38.1,50.48) v1(38.1,37.12) v1(38.32,71.53) v1(38.25,63.16) v1(38.28,38.28) v1(38.28,31.98) v1(38.28,23.1) v1(38.43,29.65) v1(38.48,52.62) v1(38.73,60.01) v1(38.73,43.16) v1(39.2,46.28) v1(39.22,22.25) v1(39.52,25.53) v1(39.48,23.45) v1(39.59,69.57) v1(39.57,27.53) v1(40,65.91) v1(39.98,35.37) v1(40.09,60.07) v1(40.11,50.62) v1(40.22,28.9) v1(40.25,68.84) v1(40.61,66.78) v1(40.57,43.28) v1(40.57,33.43) v1(40.73,22.26) v1(40.77,45.16) v1(41,66.01) v1(41.17,69.59) v1(41.38,71.99) v1(41.47,26.62) v1(41.56,60.12) v1(41.73,68.74) v1(41.73,66.89) v1(41.67,64.01) v1(41.69,62.26) v1(41.71,37.14) v1(42.16,52.05) v1(42.27,73.86) v1(42.3,25) v1(42.26,23.55) v1(42.28,22.23) v1(42.38,75.3) v1(42.44,69.45) v1(42.53,45.98) v1(42.61,43.37) v1(42.65,29.43) v1(42.92,66.97) v1(42.88,65.43) v1(42.93,24.26) v1(43.07,63.12) v1(43.11,31.37) v1(43.23,59.95) v1(43.15,33.37) v1(43.26,37.97) v1(43.27,35.68) v1(43.28,27.38) v1(43.36,76.3) v1(43.36,73.11) v1(43.44,46.32) v1(44.05,32.03) v1(44.11,72.18) v1(44.12,55.53) v1(44.07,44.12) v1(44.07,22.25) v1(44.23,69.68) v1(44.28,59.93) v1(44.36,57.22) v1(44.52,75.41) v1(44.48,52.03) v1(44.59,34.51) v1(44.8,72.93) v1(44.75,47.95) v1(44.81,36.19) v1(44.97,45.85) v1(45.15,46.82) v1(45.19,73.95) v1(45.2,51.03) v1(45.4,64.61) v1(45.53,60.01) v1(45.55,33.68) v1(45.77,38.03) v1(45.94,76.41) v1(45.9,53.58) v1(45.91,43.42) v1(45.91,22.25) v1(46.15,73.01) v1(46.19,72.09) v1(46.18,49.12) v1(46.22,46.05) v1(46.34,64.64) v1(46.55,56) v1(46.59,36.75) v1(46.68,51.48) v1(47.11,25.99) v1(47.21,71.93) v1(47.16,33.36) v1(47.4,74.97) v1(47.35,35.23) v1(47.55,56.32) v1(47.67,64.66) v1(47.72,55.65) v1(47.91,22.25) v1(48.25,76.84) v1(48.44,73.82) v1(48.72,56.12) v1(49.23,72.96) v1(49.61,64.33) v1(49.61,27.32) v1(49.92,62.39) v1(49.9,29.18) v1(49.91,22.25) v1(49.95,76.93) v1(50.02,72.14) v1(50.1,61.39) v1(50.27,75.24) v1(50.48,65.64) v1(50.71,64.51) v1(50.69,32.52) v1(50.75,23.25) v1(50.82,35.93) v1(51.07,65.6) v1(51.09,60.89) v1(51.66,76.89) v1(51.86,61.35) v1(51.91,22.25) v1(52.42,74.93) v1(52.73,72.41) v1(52.73,67.59) v1(52.83,76.97) v1(52.82,60.97) v1(52.88,69.78) v1(53.67,65.41) v1(53.9,63.83) v1(53.91,22.25) v1(54.05,32.14) v1(54.11,29.24) v1(54.21,68.45) v1(54.48,72.28) v1(54.69,70.53) v1(54.78,64.51) v1(55.29,23.61) v1(55.71,33.4) v1(55.7,30.99) v1(55.92,39.69) v1(55.92,35.55) v1(55.94,26.74) v1(55.91,22.25) v1(55.97,38.01) v1(56.17,69.8) v1(56.28,72.2) v1(57.1,59.81) v1(57.56,73.3) v1(57.57,72.29) v1(57.57,71.29) v1(57.57,69.79) v1(57.69,57.87) v1(57.69,55.87) v1(57.69,53.87) v1(57.69,51.87) v1(57.69,49.87) v1(57.69,47.87) v1(57.69,45.87) v1(57.69,43.87) v1(57.69,41.87) v1(57.69,39.87) v1(57.69,37.87) v1(57.69,35.87) v1(57.69,33.87) v1(57.69,31.87) v1(57.69,29.87) v1(57.69,27.87) v1(57.69,25.87) v1(57.69,23.87) v1(57.79,22.25) v2(27.25,42.15) v2(27.25,41.15) v2(27.25,40.15) v2(27.25,39.15) v2(28.25,42.15) v2(28.25,41.15) v2(28.25,40.15) v2(28.25,39.15) v2(29.25,42.15) v2(29.25,41.15) v2(29.25,40.15) v2(29.25,39.15) v2(30.25,42.15) v2(30.25,41.15) v2(30.25,40.15) v2(30.25,39.15)
VDDR: length 45
  TOP w0.15: C107.1 27.85,37.33 28,37.48 U1.27
  TOP w0.25: U1.1 31.22,38.57
  TOP w0.35: v1(32.72,38.3) C106.1 31.5,38.3 31.22,38.57 ; C107.1 27.65,36.95 27.59,36.89 27.51,36.89 27.32,36.7 27.32,36.67 26.68,36.02 26.68,35.98 25.14,34.44 25.14,34.37 v1(24.75,33.98)
  TOP w0.5: v1(33.75,43.78) 33.75,44.71 30.96,47.5 20.82,47.5
  BOTTOM w0.5: v1(20.02,47.53) 19.89,47.39 19.89,38.62 ; v1(33.98,42.94) 34.33,42.58 34.33,39.31 33.32,38.3 v1(32.72,38.3) ; v1(23.92,33.57) 23.78,33.43 21.45,33.43 19.85,35.03 v1(19.85,37.88)
  vias: v1(19.9,38.62) v1(20.39,47.14) v1(20.57,38.62) v1(20.55,37.85) v1(20.66,47.54) v1(20.91,47.12) v1(24.28,33.95) v1(24.45,33.52) v1(33.6,43.31) v1(34.12,43.44)
VDDS: length 61.6
  TOP w0.15: U1.14 C101.1 ; U1.6 31.8,41.38 32.13,41.7 C99.1 ; U1.30 29.5,37.12 29.3,36.93 C102.1
  TOP w0.2: U1.25 26.57,38.15
  TOP w0.3: C101.1 27.76,44.08 27.32,44.52 v1(27.32,45.1) ; 26.57,38.15 26.28,37.85
  TOP w0.35: C102.1 29.3,31.85 29.12,31.67 29.12,31.66 28.81,31.36 25.17,31.36 23.38,33.15 v1(23.38,34.15) ; C99.1 32.45,41.73 32.45,42.2 32.32,42.33 32.32,43.5 32.22,43.61 v1(32.22,44.11) ; v1(26.08,48.45) 26.12,48.45 26.15,48.49 26.19,48.45 R1.2 ; 26.28,37.85 26.25,37.83 C103.1 26.25,36.3 26.18,36.23 26.18,36.2 25.07,35.1 C104.1
  TOP w0.5: v1(26.71,45.75) 26.68,45.72 26.27,45.72 26.27,45.72 v1(22,45.72) ; B1.1 21.93,50.55 24.03,48.45 v1(25.54,48.45)
  BOTTOM w0.5: v1(26.71,45.75) 26.72,45.76 26.72,47.8 v1(26.08,48.45) ; v1(27.17,45.61) 27.34,45.78 30.17,45.78 31.16,44.79 v1(31.63,44.79) ; 21.75,34.19 20.7,35.24 20.7,36.6 21.43,37.33 21.43,39.18 20.69,39.91 20.69,45.71 v1(21.11,46.13)
  vias: v1(21.47,45.75) v1(21.75,46.15) v1(21.78,34.18) v1(22.3,34.18) v1(22.83,34.18) v1(25.57,48.94) v1(26.08,48.95) v1(26.83,45.3) v1(31.71,44.27) v1(32.13,44.63)
BP_RESET: length 27.9
  TOP w0.15: J2.11 50.95,46.18 53.38,46.18 53.53,46.33 53.53,58.1 52.97,58.65 48.1,58.65 45.73,56.28 R52.1
BTN1: length 47.4
  TOP w0.15: v1(11.38,32.62) 5.9,32.62 3.07,35.45 3.07,41.23 2.8,41.5 2.8,58.53 6.12,61.85 6.53,61.85 7.55,62.88 7.55,63.4 7.03,63.92 R56.2 ; v1(11.38,33.55) 11.38,34.7 13.6,36.93 P6.3
  BOTTOM w0.15: v1(11.38,33.55) v1(11.38,32.62)
BTN2: length 38
  TOP w0.15: v1(46.68,46.43) 46.68,47.6 45,49.27 P7.3 ; v1(55.6,45.93) 55.6,50.12 56.27,50.8 56.27,52.53 55.65,53.15 55.65,59.75 53.85,61.55 52.28,61.55 52.07,61.75 52.07,63.5 52.3,63.72 R55.2
  BOTTOM w0.15: v1(55.6,45.93) 47.18,45.93 v1(46.68,46.43)
DIO1_RTS: length 58.5
  TOP w0.15: U1.18 25.67,41.88 23.42,44.12 v1(18.3,44.12) ; v1(21.32,51.75) 21.32,49.05 20.9,48.62 18.8,48.62 18.62,48.45 v1(18.62,48.05) ; v1(31.55,51.43) 31.55,49.4 36.1,44.85 36.1,44.23 36.1,42.6 36.4,42.3 46.7,42.3 47.15,42.75 47.15,46.6 47.1,46.65 v1(47.1,47.35) ; v1(22.53,51.75) 22.85,51.43 v1(29.3,51.43)
  BOTTOM w0.15: J2.9 v1(47.1,47.35) ; v1(31.55,51.43) v1(29.3,51.43) ; v1(18.3,44.12) 18.62,44.45 v1(18.62,48.05) ; v1(22.53,51.75) v1(21.32,51.75)
DIO3: length 15.6
  TOP w0.15: J1.15 7.44,39.73 8.69,40.98 9.27,40.98 11.34,43.05 18.46,43.05 19.2,42.31 R6.2
DIO4: length 28.2
  TOP w0.15: R7.1 19.49,41.6 18.34,42.75 11.53,42.75 10.72,41.95 10.72,39.43 9.65,38.35 5.47,38.35 5.22,38.6 5.22,45.45 5.66,45.89 5.66,46.62 J1.9
DIO5_A2: length 90.4
  TOP w0.15: v1(4,36.08) 4,58.32 6.43,60.75 21.65,60.75 22.93,62.03 33,62.03 34.1,63.13 v1(34.1,64.23) ; v1(11.31,36.95) 11.31,39.98 11.28,40.01 11.28,40.39 11.31,40.42 v1(11.31,41.39) 12.37,42.45 18.21,42.45 21.47,39.19 25.21,39.19 25.4,39.38 U1.23
  BOTTOM w0.15: R21.1 33.68,65.58 34.1,65.16 v1(34.1,64.23) ; J1.14 9.81,41.39 v1(11.31,41.39) ; v1(4,36.08) 10.43,36.08 v1(11.31,36.95)
DIO6_FLASH_CS: length 130.2
  TOP w0.15: v1(55.34,51.35) 55.34,51.53 55.34,51.53 55.34,51.76 55.21,51.89 55.21,56.24 55.12,56.33 55.12,59.62 54.59,60.15 46.95,60.15 46.24,59.44 38.23,59.44 v1(36.22,61.45) ; v1(17.93,64.08) v1(33.5,64.08) ; U1.26 27.5,37.7 v1(26.97,37.18) ; v1(17.9,61.58) 17.5,61.58 17.47,61.55 6.35,61.55 3.15,58.35 3.15,41.62 3.57,41.2 3.57,35.38 5.84,33.11 20.12,33.11 20.4,32.83 v1(20.43,32.83) ; U3.1 R24.1 16.32,66.29 16.84,66.8 v1(17.05,66.8)
  BOTTOM w0.15: J2.5 50.95,51.07 55.06,51.07 v1(55.34,51.35) ; v1(33.5,64.08) 35.84,61.74 35.94,61.74 v1(36.22,61.45) ; v1(26.97,37.18) 25.17,35.37 25.17,33.42 24.58,32.83 v1(20.43,32.83) ; v1(17.9,61.58) 17.9,63.65 17.93,63.67 v1(17.93,64.08) 17.93,66.25 17.38,66.8 v1(17.05,66.8)
DIO8_SDA: length 15.9
  TOP w0.15: U1.2 35.28,39.38 35.4,39.25 v1(36.82,39.25) ; P7.4 P7.2 37.34,44.72 37.35,44.7 v1(37.35,42.84)
  BOTTOM w0.15: v1(36.82,39.25) 36.82,42.31 v1(37.35,42.84)
DIO11_CS: length 39.6
  TOP w0.15: U1.3 33.19,39.88 33.29,39.77 47.31,39.77 48.41,38.68 50.02,38.68 50.89,39.55 50.89,40.19 51.48,40.78 52.89,40.78 55.12,43.01 55.12,50.27 55.77,50.92 55.77,51.53 55.64,51.66 v1(55.64,52.11)
  BOTTOM w0.15: v1(55.64,52.11) 55.33,52.42 53.16,52.42 53.15,52.43 J2.6
DIO12_MISO: length 82.9
  TOP w0.15: v1(33,63.58) 32.6,63.58 32.52,63.65 17.75,63.65 17.74,63.66 17.35,63.66 17.15,63.85 v1(16.75,63.85) ; v1(35.8,60.93) 36.2,60.93 37.99,59.14 39.65,59.14 39.66,59.14 40.06,59.14 40.61,58.59 41.08,58.59 41.2,58.71 46.39,58.71 46.46,58.78 46.49,58.78 47.26,59.55 53.45,59.55 54.52,58.48 54.52,56.08 54.55,56.05 54.55,50.81 54.52,50.77 54.52,43.59 53.19,42.27 J2.14 51.09,42.27 49.96,41.13 49.35,41.13 48.41,40.19 33.58,40.19 33.39,40.38 U1.4 ; U3.2 16.78,65.62 v1(16.75,65.6)
  BOTTOM w0.15: v1(33,63.58) 33.55,63.03 33.6,63.03 35.41,61.21 35.52,61.21 v1(35.8,60.93) ; v1(16.75,63.85) v1(16.75,65.6)
DIO13_MOSI: length 76.8
  TOP w0.15: U3.5 20.9,64.62 21.02,64.5 v1(21.43,64.5) ; U1.5 31.85,40.88 32.01,40.72 47.62,40.72 48.52,41.62 48.52,42.96 49.09,43.54 50.85,43.54 J2.12 53.19,44.81 53.9,45.53 53.9,58.15 53.1,58.95 47.53,58.95 46.5,57.93 38.66,57.93 36.16,60.43 v1(35.32,60.43) ; v1(32.6,63.1) 32.2,63.1 31.98,63.31 22.04,63.31 21.83,63.1 v1(21.43,63.1)
  BOTTOM w0.15: v1(35.32,60.43) 33.18,62.58 33.12,62.58 v1(32.6,63.1) ; v1(21.43,63.1) v1(21.43,64.5)
DIO14_RLED: length 77.5
  TOP w0.15: J2.3 47.99,53.37 47.99,48.87 47.97,48.86 47.97,48.32 47.87,48.22 47.87,42.12 47.36,41.61 34.69,41.61 34.12,42.18 34.12,42.29 33.99,42.42 33.86,42.42 32.82,43.45 32.82,44.54 32.13,45.23 31.47,45.23 31.2,44.97 31.2,44.01 31.85,43.36 31.85,42.13 31.59,41.88 U1.7 ; P2.2 46.38,31.06 50.86,31.06 53.47,33.68 53.47,40.48 56.39,43.39 56.39,49.34 56.98,49.93 56.98,53.26 56.23,54.01 v1(56.23,56.06)
  BOTTOM w0.15: v1(56.23,56.06) 55.83,56.06 55.79,56.02 50.63,56.02 J2.3
DIO18_SCLK: length 72.9
  TOP w0.15: v1(20.62,65.08) 20.57,65.12 U3.6 ; v1(3.57,42.27) 3.57,58.33 6.4,61.15 18.08,61.15 18.5,61.58 v1(20.62,61.58) 22.02,61.58 22.93,62.48 v1(31.06,62.48) ; v1(29.72,50.94) 29.72,56.67 31.35,58.3 v1(31.35,59.62) ; U1.10 30,43.7 30.2,43.9 30.2,46.23 29.8,46.62 v1(29.8,46.88)
  BOTTOM w0.15: v1(29.72,50.94) 29.72,50.28 29.8,50.2 v1(29.8,46.88) ; v1(31.06,62.48) 31.35,62.2 31.35,62 31.35,62 v1(31.35,59.62) ; J1.13 v1(3.57,42.27) ; v1(20.62,61.58) v1(20.62,65.08)
DIO19_GLED: length 68.6
  TOP w0.15: v1(35.05,41.14) 47.62,41.14 48.2,41.73 48.2,47.77 49.02,48.59 50.82,48.59 J2.8 ; P2.4 48.59,31.39 50.71,31.39 53.17,33.85 53.17,40.6 56.07,43.49 56.07,49.69 v1(56.25,49.88) ; v1(29.15,48.12) 31.45,48.12 34.68,44.9 34.68,42.78 v1(35.05,42.4) ; U1.11 29.5,43.68 29.78,43.95 29.78,43.98 29.9,44.1 29.9,46.1 v1(29.3,46.7)
  BOTTOM w0.15: v1(35.05,41.14) 35.05,41.15 v1(35.05,42.4) ; J2.8 55.56,49.89 55.57,49.9 55.82,49.9 55.85,49.88 v1(56.25,49.88) ; v1(29.15,48.12) 29.15,47.28 29.15,47.28 29.15,46.88 29.3,46.72 v1(29.3,46.7)
DIO21_CTS: length 39.1
  TOP w0.15: v1(28.23,46.47) 29.1,45.6 29.1,44.43 28.87,44.2 28.87,43.96 28.84,43.93 28.84,43.81 28.62,43.59 28.62,43.56 28.5,43.44 U1.13 ; v1(47.13,49.6) 47.13,48.68 47.53,48.28 47.53,42.49 47.01,41.98 36.1,41.98 35.03,43.05 35.03,45.08 31.53,48.58 28.68,48.58 v1(28.22,48.12)
  BOTTOM w0.15: v1(47.13,49.6) 47.42,49.89 J2.7 ; v1(28.23,46.47) 28.23,48 28.22,48.01 v1(28.22,48.12)
DIO23_A8: length 24.3
  TOP w0.15: J1.6 9.65,51.7 9.65,51.26 10.32,50.59 10.32,47.54 12.98,44.88 25.82,44.88 27,43.7 U1.16
DIO24_SCL: length 15.9
  TOP w0.15: v1(17.72,40.33) 17.53,40.33 17.26,40.05 P6.2 P6.4 ; U1.17 26.03,42.38 23.82,44.58 18.16,44.58 18.12,44.55 17.88,44.3 17.88,44.3 v1(17.72,44.15)
  BOTTOM w0.15: v1(17.72,40.33) v1(17.72,44.15)
LP_RESET: length 14.8
  TOP w0.15: R51.1 46.58,54.75 47.56,53.77 v1(47.56,49)
  BOTTOM w0.15: J2.10 50.92,48.55 48.05,48.55 47.89,48.72 47.84,48.72 v1(47.56,49)
SCL: length 52.8
  TOP w0.15: P6.1 12.38,39.48 11.75,38.85 11.75,36.79 11.1,36.14 7.43,36.14 J1.17 5.35,37.19 4.9,37.65 4.9,45.55 4.73,45.72 4.73,58.2 6.36,59.83 R67.1
SDA: length 72.5
  TOP w0.15: v1(32.2,56.73) 32.5,57.03 35.18,57.03 37.49,54.71 37.58,54.71 37.82,54.46 37.82,54.38 39.17,53.03 39.17,48.6 39.78,48 P7.1 ; R66.1 v1(23.53,60.88) 22.62,60.88 22,60.25 6.36,60.25 4.38,58.26 4.38,36.66 J1.19 ; v1(29.28,56.62) 27.47,56.62 26,58.1 v1(24.18,58.1)
  BOTTOM w0.15: v1(24.18,58.1) 24.18,60.23 v1(23.53,60.88) ; v1(29.28,56.62) 29.68,56.62 29.78,56.73 v1(32.2,56.73)
WMCU_RESET: length 93
  TOP w0.15: U1.19 25.33,41.38 23.66,43.05 21.01,43.05 20.89,42.92 v1(19.19,42.92) ; P3.11 31.32,77.05 46.2,77.05 50.72,72.53 CR8.3 51.28,71.23 51.88,70.63 51.88,68.38 49.72,66.23 48.96,66.23 48.96,65 47.93,63.98 42.5,63.98 42.35,63.83 v1(42.35,61.05) ; R51.2 R52.2 41.62,57.31 v1(41.65,57.35) 31.85,57.35 31.09,56.59 31.09,49.95 30.17,49.03 C92.1 27.7,49.03 R1.1 27.7,48.31 27.36,47.97 21.25,47.97 21.16,48.07 v1(19.18,48.07)
  BOTTOM w0.15: v1(41.65,57.35) 42.35,58.05 v1(42.35,61.05) ; v1(19.18,48.07) 19.18,43.33 19.19,43.32 v1(19.19,42.92)
WMCU_RXD: length 80.3
  TOP w0.15: P3.7 23.78,74.58 23.78,70.62 v1(26.53,67.88) ; v1(29.5,58.6) 5.99,58.6 5.33,57.95 5.33,53.48 J1.5 7.52,53.57 9.32,53.57 10.07,52.81 10.07,51.26 10.68,50.65 10.68,47.65 13.08,45.25 17.87,45.25 17.87,45.25 18.73,45.25 18.73,45.25 25.96,45.25 27.5,43.7 U1.15
  BOTTOM w0.15: v1(26.53,67.88) 26.64,67.76 26.99,67.76 27.47,67.28 27.9,67.28 29.78,65.39 29.78,58.89 v1(29.5,58.6)
WMCU_SWDCK: length 63.4
  TOP w0.15: v1(30.2,50.49) 30.2,56.7 38.4,64.9 39.59,64.9 v1(39.6,64.89) ; v1(30.33,46.88) 30.33,46.52 30.5,46.35 U1.9 ; CR8.6 48.77,70.73 48.34,70.29 v1(48.34,69.33) ; v1(45.15,69.11) 45.15,68.71 45.15,68.71 45.15,65.48 44.24,64.58 42.45,64.58 42.2,64.82 v1(42.2,64.89) 42.19,64.9 41.43,64.9 40.88,64.35 R5.2
  BOTTOM w0.15: v1(30.2,50.49) 30.2,47.17 30.32,47.04 30.32,46.88 v1(30.33,46.88) ; v1(39.6,64.89) 40,64.89 40.02,64.91 42.19,64.91 v1(42.2,64.89) ; P3.15 36.35,77 44.35,77 48.34,73 48.34,69.33 v1(48.34,69.33) 45.93,69.33 45.71,69.11 v1(45.15,69.11)
WMCU_SWDIO: length 59.2
  TOP w0.15: v1(49.32,68.62) 49.32,69.03 49.32,69.04 CR8.7 ; R4.2 39.45,63.97 39.23,64.2 ; v1(30.84,46.74) 30.84,43.91 31.22,43.52 U1.8 ; 39.23,64.2 40.27,64.2 42.3,66.23 43.88,66.23 43.88,68.21 43.87,68.21 v1(43.87,68.62) ; 39.23,64.2 v1(38.82,64.2) 38.81,64.21 38.26,64.21 30.62,56.58 v1(30.62,50.13)
  BOTTOM w0.15: v1(38.82,64.2) 38.82,64.2 38.82,72.9 38.87,72.95 38.87,74.13 38.45,74.55 35.17,74.55 33.79,75.93 P3.13 ; v1(30.62,50.13) 30.62,47.35 30.84,47.14 v1(30.84,46.74) ; v1(49.32,68.62) v1(43.87,68.62)
WMCU_TXD: length 85.3
  TOP w0.15: J1.7 5.03,51.24 5.03,58.07 6.16,59.2 26.84,59.2 27.01,59.03 v1(30.25,59.03) ; v1(10.98,50.95) 10.98,47.85 13.23,45.6 19.81,45.6 20.88,46.67 21.31,46.67 21.53,46.89 28.49,46.89 29.47,45.91 29.47,44.08 29.15,43.75 29.15,43.61 29.12,43.59 29.12,43.51 29,43.39 U1.12 ; P3.9 26.55,74.81 26.55,68.8 v1(27.65,67.7)
  BOTTOM w0.15: J1.7 7.44,50.95 v1(10.98,50.95) ; v1(30.25,59.03) 30.25,59.43 30.43,59.6 30.43,65.33 28.05,67.7 v1(27.65,67.7)
WMCU_VDD: length 152.2
  TOP w0.15: 17.88,68.62 17.9,68.65 ; v1(46.14,67.75) 46.14,68.15 46.15,68.16 46.15,68.2 46.18,68.23 CR9.8 ; v1(50.02,67.76) 50.02,68.23 50.03,68.24 CR8.8 ; 22.43,68.38 v1(22.45,68.4) ; R23.1 15.87,67.05 R24.2
  TOP w0.3: P4.1 43.88,63.2 44.12,63.45 50.82,63.45 v1(52.38,65.01)
  TOP w0.5: v1(26.5,56.93) 25.78,56.2 B1.2 21.04,56.2 21.03,56.2 7.7,56.2 J1.1 ; 25.9,60.38 25.73,60.55 25.71,60.55 25.38,60.88 R66.2 ; 25.9,60.38 v1(28.38,60.38) 32.9,60.38 40.28,67.76 v1(41.49,67.76) ; 25.9,60.38 25.9,60.04 25.69,59.83 R67.2 ; R25.2 17.88,68.62 ; R23.1 14.78,67.95 15.47,68.65 22.2,68.65 v1(22.45,68.4) ; R22.1 22.43,68.38
  BOTTOM w0.5: v1(26.5,56.93) 28.38,58.8 v1(28.38,60.38) ; P1.1 56.95,29.75 56.95,58.53 52.38,63.1 52.38,64.43 52.38,64.43 v1(52.38,65.01) 52.38,65.95 50.59,67.74 50.04,67.74 v1(50.02,67.76) 46.55,67.76 46.54,67.75 v1(46.14,67.75) 41.9,67.75 41.9,67.76 v1(41.49,67.76)
  BOTTOM w0.55: 24.06,69.31 21.33,72.04 21.33,74.68 P3.5 ; 24.06,69.31 26.12,67.25 26.79,67.25 29.1,64.94 29.1,61.1 v1(28.38,60.38) ; 24.06,69.31 23.36,69.31 v1(22.45,68.4)
XDS_BOARDID_SCL: length 12.2
  TOP w0.15: P3.6 21.55,73.38 19.67,71.5 13.85,71.5 12.22,73.12 U4.1
XDS_BOARDID_SDA: length 7.5
  TOP w0.15: P3.4 18.48,71.82 15.43,71.82 14.12,73.12 U4.3
XDS_GPIO3: length 22.6
  TOP w0.15: CR9.7 33.36,70.23 P3.12
  BOTTOM w0.15: P3.12 33.68,69.91 R21.2
N3101199: length 6.2
  TOP w0.15: U1.20 25.33,40.88 24.71,41.5 24.39,41.5 23.61,42.28 Y1.1 22.79,42.28 22.44,42.63 C81.1 21.91,42.63 21.9,42.64 21.22,42.64 R6.1
N3101441: length 6
  TOP w0.15: C52.1 28.21,32.99 Y2.1 28.75,34.11 28.75,37.3 29,37.55 U1.29
N3101453: length 7
  TOP w0.15: C53.1 26.3,33.78 Y2.3 26.34,33.81 26.34,34.79 26.93,35.38 28.14,35.38 28.43,35.66 28.43,37.4 28.5,37.47 U1.28
N3109894: length 38.1
  TOP w0.15: v1(39.47,58.72) 39.96,58.24 46.39,58.24 47.4,59.25 53.32,59.25 54.22,58.36 54.22,55.96 54.25,55.93 54.25,50.93 54.22,50.9 54.22,44.27 53.53,43.58 51.92,43.58 50.61,42.27 J2.13 ; R4.1 39.45,60.7 v1(39.47,60.68)
  BOTTOM w0.15: v1(39.47,58.72) v1(39.47,60.68)
N3109960: length 39.4
  TOP w0.15: v1(40.9,60.7) 40.88,60.73 R5.1 ; J2.15 50.93,41.08 52.56,41.08 54.82,43.34 54.82,50.65 54.85,50.68 54.85,56.18 54.82,56.21 54.82,58.76 53.72,59.85 47.1,59.85 46.26,59.01 v1(40.9,59.01)
  BOTTOM w0.15: v1(40.9,59.01) v1(40.9,60.7)
N3110356: length 2.5
  TOP w0.15: R14.2 45.28,27.51 45.32,27.56 P2.1
N3110380: length 2.7
  TOP w0.15: P2.3 47.87,27.4 47.85,27.39 R15.2
N3110768: length 2.9
  TOP w0.15: R56.1 6.57,62.54 6.29,62.25 SW1.4
N3110772: length 1.8
  TOP w0.15: R55.1 52.75,62.79 53.31,62.23 SW2.3
N3110876: length 1.4
  TOP w0.15: CR1.2 47.85,25.23 47.85,25.23 R15.1
N3110880: length 1.5
  TOP w0.15: R14.1 45.28,25.25 CR2.2
N3111246: length 3.3
  TOP w0.15: C55.1 20.57,67.4 20.25,67.73 R25.1
  TOP w0.25: U3.8 C55.1
N3111262: length 2.8
  TOP w0.15: U3.7 21.47,65.62 21.72,65.88 22.43,65.88
N3111266: length 2.7
  TOP w0.15: R23.2 15.48,65.45 15.8,65.12 U3.3
N3241033: length 6.3
  TOP w0.15: U1.21 25.41,40.38 24.6,41.18 Y1.2 22.67,41.18 22.44,40.96 C91.1 21.52,40.96 21.52,40.96 21.14,40.96 20.91,41.19 R7.2
N3275984: length 4.4
  TOP w0.35: CA1.2 33.24,34.83
  TOP w0.81: 33.24,34.83 J7.1
N3375988: length 1.5
  TOP w0.35: CA2.2 31.97,35.46 C34.2 31.36,36.07 L33.2
N3377063: length 9.8
  TOP w0.35: CA2.1 31.97,33.6 CR10.2 31.95,33 ; Z61.2 31.96,25.11 Z60.1 31.96,25.84 31.95,25.85
  TOP w0.81: 31.95,25.85 31.95,33
N3377070: length 1.6
  TOP w0.35: Z61.1 31.96,23.29 Z62.1 31.97,23.27 ANT1.1
N3512302: length 2.1
  TOP w0.35: U1.31 30,37.43 C33.2 30.97,36.47 L33.1
N3566095: length 2
  TOP w0.25: C9.1 24.85,39.68 25.05,39.88 U1.22

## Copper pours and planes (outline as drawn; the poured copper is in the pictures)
GND on TOP (solid shape): 29.09,21.29 30.28,21.29 30.28,22.03 31.28,22.03 31.28,20 23.28,20 23.28,17.33 29.09,17.33 29.09,18.12 28.09,18.12 28.09,19.34 31.21,19.34 31.74,20.09 31.74,22.03 32.19,22.03 32.19,19.95 31.28,18.63 31.28,18.12 30.28,18.12 30.28,16.33 46.69,16.33 46.69,15.12 21.1,15.12 21.1,21.29 28.09,21.29 28.09,22.03 29.09,22.03
VDDR on TOP: 33.35,44.06 33.35,43.24 33.99,42.6 34.08,42.6 34.34,42.87 34.34,43.69 33.96,44.07 33.36,44.07
VDDR on TOP: 19.82,47.75 19.82,47.21 20.19,46.84 21.16,46.84 21.24,46.92 21.24,47.52 21,47.75
VDDR on TOP: 24,38.98 24,37.5 23.49,36.48 22.15,36.48 22.15,37.58 19.55,37.58 19.55,38.98
VDDR on TOP: 24.94,34.11 24.94,33.62 24.61,33.29 23.75,33.29 23.68,33.35 23.68,33.87 23.98,34.17 24.94,34.17
VDDR on BOTTOM: 19.53,38.98 19.53,37.58 21.15,37.58 21.15,38.98
VDDR on BOTTOM: 19.82,47.75 19.81,47.22 20.19,46.84 21.19,46.84 21.24,46.89 21.24,47.52 20.99,47.75
VDDR on BOTTOM: 33.35,44.09 33.35,43.26 34,42.61 34.1,42.61 34.35,42.86 34.35,43.68 33.97,44.06 33.97,44.07 33.95,44.09
VDDR on BOTTOM: 24.95,34.16 23.97,34.16 23.69,33.88 23.69,33.34 23.73,33.29 24.62,33.29 24.95,33.62
VDDS on TOP: 26.51,45.97 26.5,45.2 26.79,44.89 27.45,44.89 27.56,45.1 27.51,45.45 27.22,45.97
VDDS on TOP: 23.9,35.53 21.55,34.76 21.55,33.9 23.72,33.9
VDDS on TOP: 31.43,45.01 31.43,44.22 31.77,43.88 32.47,43.88 32.47,44.71 32.16,45.02 31.44,45.02
VDDS on TOP: 20.82,46.39 20.82,45.85 21.19,45.48 22.16,45.48 22.24,45.55 22.24,46.15 22,46.39
VDDS on BOTTOM: 23.72,34.45 21.55,34.45 21.55,33.9 23.72,33.9
VDDS on BOTTOM: 26.5,45.98 26.5,45.2 26.82,44.88 27.45,44.89 27.56,45.1 27.5,45.46 27.25,45.98
VDDS on BOTTOM: 31.42,45.02 31.42,44.23 31.78,43.88 32.46,43.88 32.47,43.88 32.47,44.71 32.16,45.02 31.43,45.02
VDDS on BOTTOM: 20.81,46.4 20.81,45.86 21.18,45.49 22.16,45.49 22.23,45.55 22.23,46.15 22,46.38 22,46.4
DCDC on TOP: 26.68,39.03 24.57,39.03 24.57,37.68 24.6,37.65 25.62,37.65 25.93,37.95 25.93,38.48 26.18,38.73 26.68,38.73

Small or netless copper shapes (teardrops, artwork), in the pictures only: 2 on TOP, 2 on BOTTOM

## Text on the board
Ref Des/Silkscreen Bottom: J1 | 1 | 10 | 21 | 30 | J3 | J4 | 31 | 40 | 11 | 20 | J2
User.Comments: Rev. E2 | Milling tool 2.0 mm TYP | RED | BOTTOM LAYER
Ref Des/Silkscreen Top: J1 | 10 | 1 | 21 | 30 | J3 | J4 | 40 | 31 | 20 | 11 | J2 | DIO22 | DIO20 | DIO4 | DIO3 | DIO23 | DIO5 | BTN1 | SCL | DIO24 | CC-ANTENNA-DK | Mount for: | DIO8 | || | Green: | DIO19 | DIO14 | Red: | SDA | BTN2 | DIO21 | DIO6 | DIO1 | BPRST | DIO11 | LPRST | DIO13 | DIO12 | DIO18 | SWDIO | SWDCK | GND | 5V | 3V3 | RXD | TXD | nRST | GPIO3 | GPIO2 | GPIO1 | BTN-2 | LP-EM-CC2340R5-Q1 | Rev:E1 | BTN-1
XSECTION_CHART: *  SURFACE - AIR 0 MM | L1 TOP CONDUCTOR - COPPER 0.035 MM | *  DIELECTRIC - FR-4 0.73 MM | L2 BOTTOM CONDUCTOR - COPPER 0.035 MM | DESIGN CROSS SECTION CHART | ___________________________ | TOTAL THICKNESS 0.8 MM | 1-2
PAGE_OUTLINE: LP-EM-CC2340R5-Q1 | N/A
User.28: FIGURE | FINISHED_SIZE | 0.2 | 0.201 | 1.05 | 1.1 | 3.2 | 0.899 | DRILL CHART: TOP to BOTTOM | ALL UNITS ARE IN MILLIMETERS | PLATED | NON-PLATED | QTY | 691 | 16 | 70 | 1 | 4 | 2
